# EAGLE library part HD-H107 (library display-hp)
LED DISPLAY + - 1/2 character, decimal point right
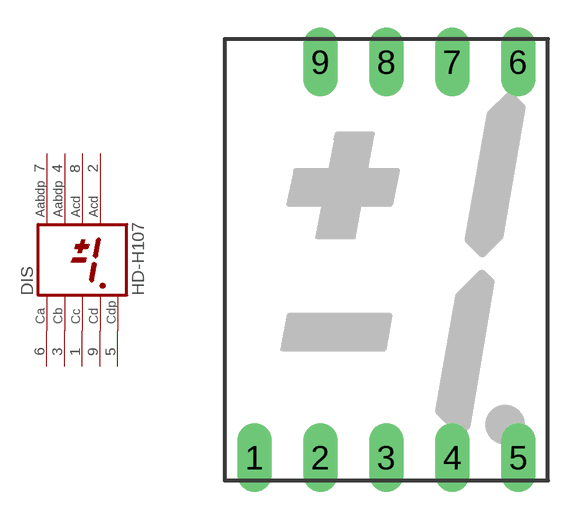
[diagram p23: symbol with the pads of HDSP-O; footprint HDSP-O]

Designator prefix DIS

## HD-H107 (OC_FARNELL: unknown; OC_NEWARK: unknown)  [HDSP-O]
1  CC  pas
2  ACD  pas
3  CB  pas
4  AABDP  pas
5  CDP  pas
6  CA  pas
7  AABDP  pas
8  ACD  pas
9  CD  pas

## Footprint HDSP-O (pad centres in mm)
LED DISPLAY 15-mm + - 1/2 character, decimal point right
drill 0.813 long: 1 -5.08,-7.62; 2 -2.54,-7.62; 3 0,-7.62; 4 2.54,-7.62; 5 5.08,-7.62; 6 5.08,7.62; 7 2.54,7.62; 8 0,7.62; 9 -2.54,7.62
